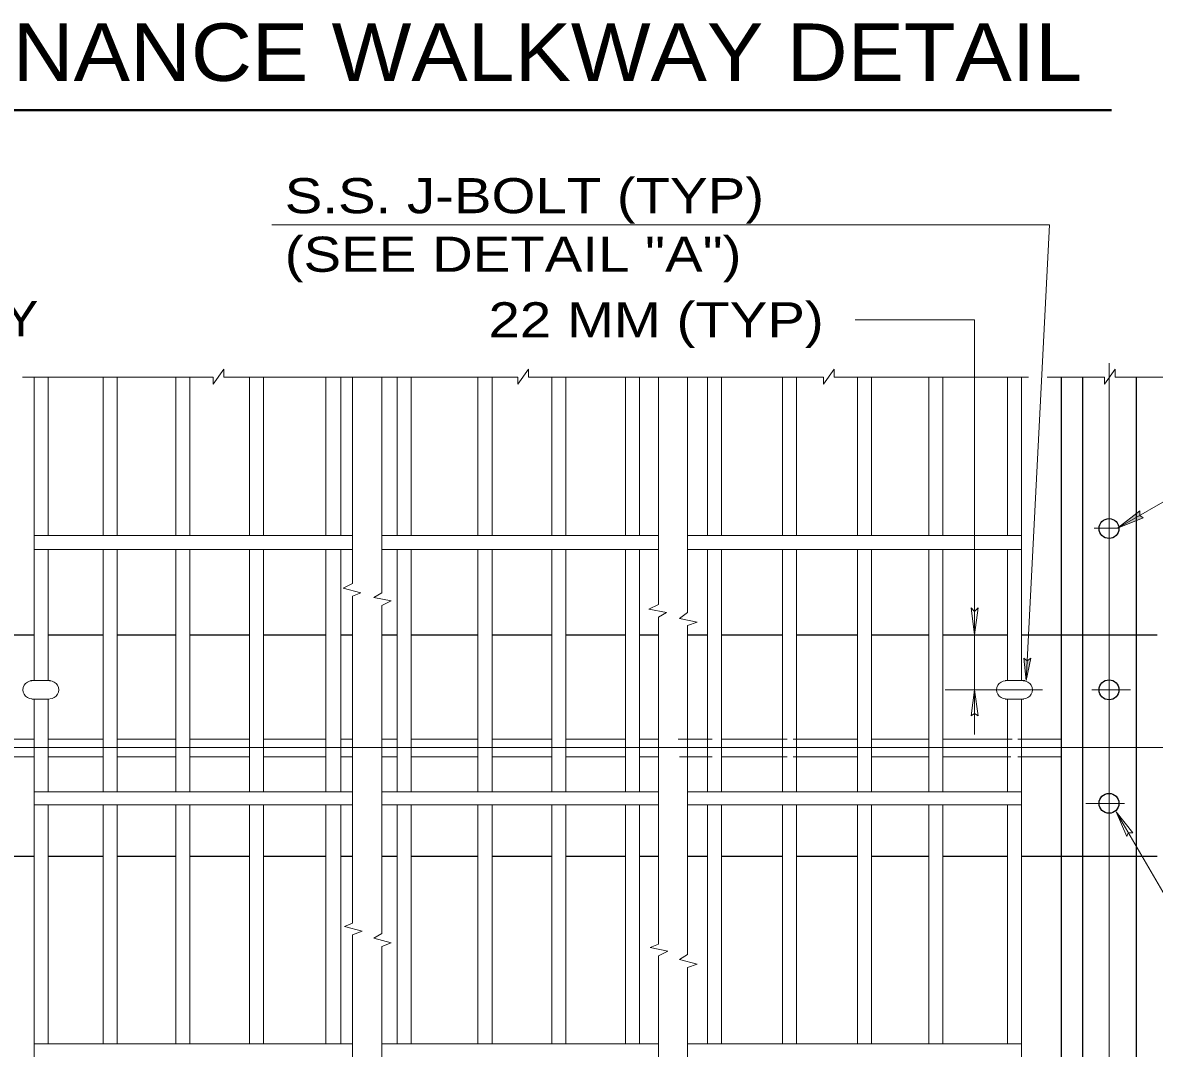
# Model space of a CAD drawing. Extents: x 312601.858 to 312602.699, y 144420.109 to 144420.704.
# Drawn here: x 312602.0138 to 312602.1105, y 144420.3668 to 144420.4544 of the extents above; entities that cross this region are included whole.
import ezdxf

# ---------------------------------------------------------------- set-up
doc = ezdxf.new("R2010")
doc.units = 0
doc.header["$LTSCALE"] = 0.0012
doc.linetypes.add('DOT_DASHED', pattern=[7.7, 5, -1.2, 0.3, -1.2])
doc.linetypes.add('LONG_DASHED', pattern=[7.5, 6, -1.5])
for name, color, linetype, lineweight in [('1', 7, 'Continuous', 13), ('2', 7, 'Continuous', 13), ('39', 7, 'Continuous', 13)]:
    doc.layers.add(name, color=color, linetype=linetype, lineweight=lineweight)

msp = doc.modelspace()

# ---------------------------------------------------------------- hatches: boundary and pattern name
at = {"layer": '39'}
for points in [[(312602.1092, 144420.4123), (312602.1095, 144420.4121), (312602.1073, 144420.4112), (312602.1092, 144420.4127)], [(312602.0996, 144420.3999), (312602.0999, 144420.4001), (312602.0995, 144420.3982), (312602.0993, 144420.4001)]]:
    msp.add_hatch(color=256, dxfattribs=at).paths.add_polyline_path(points)

# ---------------------------------------------------------------- linework, layer by layer
at = {"layer": '1'}
for p, q in [((312602.0849, 144420.429), (312602.0951, 144420.429)), ((312602.0138, 144420.4241), (312602.0301, 144420.4241)), ((312602.0148, 144420.3982), (312602.0148, 144420.4241)), ((312602.016, 144420.4106), (312602.016, 144420.4241)), ((312602.0207, 144420.4106), (312602.0207, 144420.4241)), ((312602.0219, 144420.4106), (312602.0219, 144420.4241)), ((312602.0269, 144420.4106), (312602.0269, 144420.4241)), ((312602.0281, 144420.4106), (312602.0281, 144420.4241)), ((312602.0301, 144420.4235), (312602.031, 144420.4248)), ((312602.0301, 144420.4235), (312602.0301, 144420.4241)), ((312602.031, 144420.4241), (312602.031, 144420.4248)), ((312602.031, 144420.4241), (312602.0407, 144420.4241)), ((312602.0332, 144420.4106), (312602.0332, 144420.4241)), ((312602.0344, 144420.4106), (312602.0344, 144420.4241)), ((312602.0397, 144420.4106), (312602.0397, 144420.4241)), ((312602.0406, 144420.4241), (312602.0561, 144420.4241)), ((312602.041, 144420.4106), (312602.041, 144420.4241)), ((312602.042, 144420.4241), (312602.042, 144420.4065)), ((312602.0445, 144420.4241), (312602.0445, 144420.4057)), ((312602.0458, 144420.4106), (312602.0458, 144420.4241)), ((312602.047, 144420.4106), (312602.047, 144420.4241)), ((312602.0527, 144420.4106), (312602.0527, 144420.4241)), ((312602.0539, 144420.4106), (312602.0539, 144420.4241)), ((312602.0561, 144420.4235), (312602.057, 144420.4248)), ((312602.0561, 144420.4235), (312602.0561, 144420.4241)), ((312602.057, 144420.4241), (312602.057, 144420.4248)), ((312602.057, 144420.4241), (312602.0822, 144420.4241)), ((312602.059, 144420.4106), (312602.059, 144420.4241)), ((312602.0602, 144420.4106), (312602.0602, 144420.4241)), ((312602.0653, 144420.4106), (312602.0653, 144420.4241)), ((312602.0665, 144420.4106), (312602.0665, 144420.4241)), ((312602.0681, 144420.4241), (312602.0681, 144420.4047)), ((312602.0706, 144420.4241), (312602.0706, 144420.404)), ((312602.0723, 144420.4106), (312602.0723, 144420.4241)), ((312602.0735, 144420.4106), (312602.0735, 144420.4241)), ((312602.0787, 144420.4106), (312602.0787, 144420.4241)), ((312602.0799, 144420.4106), (312602.0799, 144420.4241)), ((312602.0822, 144420.4235), (312602.0831, 144420.4248)), ((312602.0822, 144420.4235), (312602.0822, 144420.4241)), ((312602.0831, 144420.4241), (312602.0831, 144420.4248)), ((312602.0831, 144420.4241), (312602.0997, 144420.4241)), ((312602.0851, 144420.4106), (312602.0851, 144420.4241)), ((312602.0863, 144420.4106), (312602.0863, 144420.4241)), ((312602.0912, 144420.4106), (312602.0912, 144420.4241)), ((312602.0924, 144420.4106), (312602.0924, 144420.4241)), ((312602.0979, 144420.4106), (312602.0979, 144420.4241)), ((312602.0991, 144420.3982), (312602.0991, 144420.4241)), ((312602.1013, 144420.4241), (312602.1062, 144420.4241)), ((312602.1062, 144420.4235), (312602.1071, 144420.4248)), ((312602.1062, 144420.4235), (312602.1062, 144420.4241)), ((312602.1071, 144420.4241), (312602.1071, 144420.4248)), ((312602.1071, 144420.4241), (312602.1129, 144420.4241)), ((312602.1073, 144420.4112), (312602.1203, 144420.4187)), ((312602.0148, 144420.4106), (312602.042, 144420.4106)), ((312602.0445, 144420.4106), (312602.0681, 144420.4106)), ((312602.0706, 144420.4106), (312602.0991, 144420.4106)), ((312602.0148, 144420.4094), (312602.0208, 144420.4094)), ((312602.016, 144420.3982), (312602.016, 144420.4094)), ((312602.0207, 144420.3887), (312602.0207, 144420.4094)), ((312602.0208, 144420.4094), (312602.042, 144420.4094)), ((312602.0219, 144420.3887), (312602.0219, 144420.4094)), ((312602.0269, 144420.3887), (312602.0269, 144420.4094)), ((312602.0281, 144420.3887), (312602.0281, 144420.4094)), ((312602.0332, 144420.3887), (312602.0332, 144420.4094)), ((312602.0344, 144420.3887), (312602.0344, 144420.4094)), ((312602.0397, 144420.3887), (312602.0397, 144420.4094)), ((312602.041, 144420.3887), (312602.041, 144420.4094)), ((312602.0445, 144420.4094), (312602.0681, 144420.4094)), ((312602.0458, 144420.3887), (312602.0458, 144420.4094)), ((312602.047, 144420.3887), (312602.047, 144420.4094)), ((312602.0527, 144420.3887), (312602.0527, 144420.4094)), ((312602.0539, 144420.3887), (312602.0539, 144420.4094)), ((312602.059, 144420.3887), (312602.059, 144420.4094)), ((312602.0602, 144420.3887), (312602.0602, 144420.4094)), ((312602.0653, 144420.3887), (312602.0653, 144420.4094)), ((312602.0665, 144420.3887), (312602.0665, 144420.4094)), ((312602.0706, 144420.4094), (312602.0991, 144420.4094)), ((312602.0723, 144420.3887), (312602.0723, 144420.4094)), ((312602.0735, 144420.3887), (312602.0735, 144420.4094)), ((312602.0787, 144420.3887), (312602.0787, 144420.4094)), ((312602.0799, 144420.3887), (312602.0799, 144420.4094)), ((312602.0851, 144420.3887), (312602.0851, 144420.4094)), ((312602.0863, 144420.3887), (312602.0863, 144420.4094)), ((312602.0912, 144420.3887), (312602.0912, 144420.4094)), ((312602.0924, 144420.3887), (312602.0924, 144420.4094)), ((312602.0979, 144420.3982), (312602.0979, 144420.4094)), ((312602.0412, 144420.4061), (312602.042, 144420.4065)), ((312602.0412, 144420.4061), (312602.0427, 144420.4057)), ((312602.042, 144420.4054), (312602.0427, 144420.4057)), ((312602.042, 144420.4054), (312602.042, 144420.3775)), ((312602.0438, 144420.4053), (312602.0445, 144420.4057)), ((312602.0438, 144420.4053), (312602.0453, 144420.405)), ((312602.0445, 144420.4046), (312602.0453, 144420.405)), ((312602.0445, 144420.4046), (312602.0445, 144420.3766)), ((312602.0673, 144420.4043), (312602.0681, 144420.4047)), ((312602.0673, 144420.4043), (312602.0688, 144420.404)), ((312602.0681, 144420.4036), (312602.0688, 144420.404)), ((312602.0699, 144420.4035), (312602.0706, 144420.404)), ((312602.0681, 144420.4036), (312602.0681, 144420.3757)), ((312602.0699, 144420.4035), (312602.0714, 144420.4032)), ((312602.0706, 144420.4029), (312602.0714, 144420.4032)), ((312602.0706, 144420.4029), (312602.0706, 144420.3748)), ((312602.0145, 144420.3982), (312602.0162, 144420.3982)), ((312602.0977, 144420.3982), (312602.0994, 144420.3982)), ((312602.0146, 144420.3966), (312602.0161, 144420.3966)), ((312602.0148, 144420.3885), (312602.0148, 144420.3966)), ((312602.016, 144420.3887), (312602.016, 144420.3966)), ((312602.0977, 144420.3966), (312602.0993, 144420.3966)), ((312602.0979, 144420.3887), (312602.0979, 144420.3966)), ((312602.0991, 144420.3512), (312602.0991, 144420.3966)), ((312602.0148, 144420.3655), (312602.0148, 144420.3887)), ((312602.0148, 144420.3887), (312602.042, 144420.3887)), ((312602.0445, 144420.3887), (312602.0681, 144420.3887)), ((312602.0706, 144420.3887), (312602.0991, 144420.3887)), ((312602.0148, 144420.3876), (312602.042, 144420.3876)), ((312602.016, 144420.3672), (312602.016, 144420.3876)), ((312602.0207, 144420.3672), (312602.0207, 144420.3876)), ((312602.0219, 144420.3672), (312602.0219, 144420.3876)), ((312602.0269, 144420.3672), (312602.0269, 144420.3876)), ((312602.0281, 144420.3672), (312602.0281, 144420.3876)), ((312602.0332, 144420.3672), (312602.0332, 144420.3876)), ((312602.0344, 144420.3672), (312602.0344, 144420.3876)), ((312602.0397, 144420.3672), (312602.0397, 144420.3876)), ((312602.041, 144420.3672), (312602.041, 144420.3876)), ((312602.0445, 144420.3876), (312602.0681, 144420.3876)), ((312602.0458, 144420.3672), (312602.0458, 144420.3876)), ((312602.047, 144420.3672), (312602.047, 144420.3876)), ((312602.0527, 144420.3672), (312602.0527, 144420.3876)), ((312602.0539, 144420.3672), (312602.0539, 144420.3876)), ((312602.059, 144420.3672), (312602.059, 144420.3876)), ((312602.0602, 144420.3672), (312602.0602, 144420.3876)), ((312602.0653, 144420.3672), (312602.0653, 144420.3876)), ((312602.0665, 144420.3672), (312602.0665, 144420.3876)), ((312602.0706, 144420.3876), (312602.0991, 144420.3876)), ((312602.0723, 144420.3672), (312602.0723, 144420.3876)), ((312602.0735, 144420.3672), (312602.0735, 144420.3876)), ((312602.0787, 144420.3672), (312602.0787, 144420.3876)), ((312602.0799, 144420.3672), (312602.0799, 144420.3876)), ((312602.0851, 144420.3672), (312602.0851, 144420.3876)), ((312602.0863, 144420.3672), (312602.0863, 144420.3876)), ((312602.0912, 144420.3672), (312602.0912, 144420.3876)), ((312602.0924, 144420.3672), (312602.0924, 144420.3876)), ((312602.0979, 144420.3672), (312602.0979, 144420.3876)), ((312602.1072, 144420.387), (312602.1166, 144420.3708)), ((312602.0413, 144420.3772), (312602.042, 144420.3775)), ((312602.0413, 144420.3772), (312602.0428, 144420.3768)), ((312602.042, 144420.3765), (312602.0428, 144420.3768)), ((312602.042, 144420.3765), (312602.042, 144420.3528)), ((312602.0438, 144420.3762), (312602.0445, 144420.3766)), ((312602.0438, 144420.3762), (312602.0453, 144420.3758)), ((312602.0445, 144420.3755), (312602.0453, 144420.3758)), ((312602.0445, 144420.3755), (312602.0445, 144420.3522)), ((312602.0674, 144420.3754), (312602.0681, 144420.3757)), ((312602.0674, 144420.3754), (312602.0689, 144420.3751)), ((312602.0681, 144420.3747), (312602.0689, 144420.3751)), ((312602.0699, 144420.3744), (312602.0706, 144420.3748)), ((312602.0681, 144420.3747), (312602.0681, 144420.3476)), ((312602.0699, 144420.3744), (312602.0714, 144420.374)), ((312602.0706, 144420.3737), (312602.0714, 144420.374)), ((312602.0706, 144420.3737), (312602.0706, 144420.3473)), ((312602.0148, 144420.3672), (312602.042, 144420.3672)), ((312602.0445, 144420.3672), (312602.0681, 144420.3672)), ((312602.0706, 144420.3672), (312602.0991, 144420.3672))]:
    msp.add_line(p, q, dxfattribs=at)
at = {"layer": '1', "linetype": 'DOT_DASHED'}
for p, q in [((312602.1066, 144420.4253), (312602.1066, 144420.2757)), ((312602.1053, 144420.4112), (312602.1074, 144420.4112)), ((312602.0926, 144420.3974), (312602.1009, 144420.3974)), ((312602.1051, 144420.3974), (312602.1084, 144420.3974)), ((312601.9285, 144420.3925), (312602.0203, 144420.3925)), ((312602.0203, 144420.3925), (312602.0267, 144420.3925)), ((312602.0265, 144420.3925), (312602.1139, 144420.3925)), ((312602.1046, 144420.3877), (312602.1079, 144420.3877))]:
    msp.add_line(p, q, dxfattribs=at)
at = {"layer": '1', "lineweight": 25}
for p, q in [((312602.1025, 144420.4241), (312602.1025, 144420.3518)), ((312602.1043, 144420.4241), (312602.1043, 144420.3633)), ((312602.1089, 144420.4241), (312602.1089, 144420.3633)), ((312602.0081, 144420.4021), (312602.0148, 144420.4021)), ((312602.0219, 144420.4021), (312602.0269, 144420.4021)), ((312602.0281, 144420.4021), (312602.0332, 144420.4021)), ((312602.0344, 144420.4021), (312602.0397, 144420.4021)), ((312602.041, 144420.4021), (312602.042, 144420.4021)), ((312602.0445, 144420.4021), (312602.0458, 144420.4021)), ((312602.047, 144420.4021), (312602.0527, 144420.4021)), ((312602.0539, 144420.4021), (312602.059, 144420.4021)), ((312602.0602, 144420.4021), (312602.0653, 144420.4021)), ((312602.0665, 144420.4021), (312602.0681, 144420.4021)), ((312602.0706, 144420.4021), (312602.0723, 144420.4021)), ((312602.0735, 144420.4021), (312602.0787, 144420.4021)), ((312602.0799, 144420.4021), (312602.0851, 144420.4021)), ((312602.0863, 144420.4021), (312602.0912, 144420.4021)), ((312602.0924, 144420.4021), (312602.0979, 144420.4021)), ((312602.0991, 144420.4021), (312602.1025, 144420.4021)), ((312602.0081, 144420.3832), (312602.0148, 144420.3832)), ((312602.016, 144420.3832), (312602.0207, 144420.3832)), ((312602.0219, 144420.3832), (312602.0269, 144420.3832)), ((312602.0281, 144420.3832), (312602.0332, 144420.3832)), ((312602.0344, 144420.3832), (312602.0397, 144420.3832)), ((312602.041, 144420.3832), (312602.042, 144420.3832)), ((312602.0445, 144420.3832), (312602.0458, 144420.3832)), ((312602.047, 144420.3832), (312602.0527, 144420.3832)), ((312602.0539, 144420.3832), (312602.059, 144420.3832)), ((312602.0602, 144420.3832), (312602.0653, 144420.3832)), ((312602.0665, 144420.3832), (312602.0681, 144420.3832)), ((312602.0706, 144420.3832), (312602.0723, 144420.3832)), ((312602.0735, 144420.3832), (312602.0787, 144420.3832)), ((312602.0799, 144420.3832), (312602.0851, 144420.3832)), ((312602.0863, 144420.3832), (312602.0912, 144420.3832)), ((312602.0924, 144420.3832), (312602.0979, 144420.3832)), ((312602.0991, 144420.3832), (312602.1025, 144420.3832))]:
    msp.add_line(p, q, dxfattribs=at)
at = {"layer": '1', "linetype": 'LONG_DASHED', "lineweight": 25}
for p, q in [((312602.1025, 144420.4021), (312602.1107, 144420.4021)), ((312602.1025, 144420.3832), (312602.1107, 144420.3832))]:
    msp.add_line(p, q, dxfattribs=at)
at = {"layer": '1', "linetype": 'LONG_DASHED'}
for p, q in [((312602.0081, 144420.3932), (312602.0148, 144420.3932)), ((312602.016, 144420.3932), (312602.0207, 144420.3932)), ((312602.0219, 144420.3932), (312602.0269, 144420.3932)), ((312602.0281, 144420.3932), (312602.0332, 144420.3932)), ((312602.0344, 144420.3932), (312602.0397, 144420.3932)), ((312602.041, 144420.3932), (312602.042, 144420.3932)), ((312602.0445, 144420.3932), (312602.0458, 144420.3932)), ((312602.047, 144420.3932), (312602.0527, 144420.3932)), ((312602.0539, 144420.3932), (312602.059, 144420.3932)), ((312602.0602, 144420.3932), (312602.0653, 144420.3932)), ((312602.0665, 144420.3932), (312602.0681, 144420.3932)), ((312602.0698, 144420.3932), (312602.0727, 144420.3932)), ((312602.0735, 144420.3932), (312602.0791, 144420.3932)), ((312602.0796, 144420.3932), (312602.0851, 144420.3932)), ((312602.0863, 144420.3932), (312602.0912, 144420.3932)), ((312602.0924, 144420.3932), (312602.0983, 144420.3932)), ((312602.0988, 144420.3932), (312602.1025, 144420.3932)), ((312602.0081, 144420.3917), (312602.0148, 144420.3917)), ((312602.016, 144420.3917), (312602.0207, 144420.3917)), ((312602.0219, 144420.3917), (312602.0269, 144420.3917)), ((312602.0281, 144420.3917), (312602.0332, 144420.3917)), ((312602.0344, 144420.3917), (312602.0397, 144420.3917)), ((312602.041, 144420.3917), (312602.042, 144420.3917)), ((312602.0445, 144420.3917), (312602.0458, 144420.3917)), ((312602.047, 144420.3917), (312602.0527, 144420.3917)), ((312602.0539, 144420.3917), (312602.059, 144420.3917)), ((312602.0602, 144420.3917), (312602.0653, 144420.3917)), ((312602.0665, 144420.3917), (312602.0681, 144420.3917)), ((312602.0699, 144420.3917), (312602.0727, 144420.3917)), ((312602.0735, 144420.3917), (312602.0791, 144420.3917)), ((312602.0796, 144420.3917), (312602.0851, 144420.3917)), ((312602.0863, 144420.3917), (312602.0912, 144420.3917)), ((312602.0924, 144420.3917), (312602.0982, 144420.3917)), ((312602.0988, 144420.3917), (312602.1025, 144420.3917))]:
    msp.add_line(p, q, dxfattribs=at)
at = {"layer": '1'}
for points in [[(312602.0954, 144420.4044), (312602.0951, 144420.4021), (312602.0948, 144420.4044), (312602.0951, 144420.4041)], [(312602.0948, 144420.3952), (312602.0951, 144420.3974), (312602.0954, 144420.3952), (312602.0951, 144420.3954)], [(312602.1081, 144420.3849), (312602.1072, 144420.387), (312602.1086, 144420.3852), (312602.1082, 144420.3852)]]:
    msp.add_lwpolyline(points, close=True, dxfattribs=at)
at = {"layer": '1', "lineweight": 25}
msp.add_lwpolyline([(312602.016, 144420.4021), (312602.0172, 144420.4021), (312602.0207, 144420.4021)], dxfattribs=at)
for centre in [(312602.10658, 144420.41118), (312602.10658, 144420.39741), (312602.10658, 144420.38772)]:
    msp.add_circle(centre, 0.00085, dxfattribs=at)
at = {"layer": '1'}
for centre, start, end in [((312602.01461, 144420.39741), 89.22166, 270), ((312602.01614, 144420.39741), 270, 90.77834), ((312602.09774, 144420.39741), 89.22166, 270), ((312602.09927, 144420.39741), 270, 90.77834)]:
    msp.add_arc(centre, 0.000765, start, end, dxfattribs=at)
at = {"layer": '2', "lineweight": 40}
msp.add_line((312601.953, 144420.4469), (312602.1068, 144420.4469), dxfattribs=at)
at = {"layer": '2'}
for p in [(312602.0351, 144420.4371), (312602.0995, 144420.3982)]:
    msp.add_line(p, (312602.1015, 144420.4371), dxfattribs=at)
msp.add_lwpolyline([(312602.0951, 144420.3936), (312602.0951, 144420.3974), (312602.0951, 144420.4021), (312602.0951, 144420.429)], dxfattribs=at)
at = {"layer": '39'}
for points in [[(312602.1092, 144420.4123), (312602.1095, 144420.4121), (312602.1073, 144420.4112), (312602.1092, 144420.4127)], [(312602.0996, 144420.3999), (312602.0999, 144420.4001), (312602.0995, 144420.3982), (312602.0993, 144420.4001)]]:
    msp.add_lwpolyline(points, close=True, dxfattribs=at)

# ---------------------------------------------------------------- texts
at = {"layer": '2'}
for s, height, width, p in [('TYPICAL MAINTENANCE WALKWAY DETAIL', 0.0049, 1.1, (312601.9537, 144420.4494)), ('S.S. J-BOLT (TYP)', 0.003, 1.2, (312602.0362, 144420.4381)), ('(SEE DETAIL "A")', 0.003, 1.2, (312602.0362, 144420.4331)), ('LUMINAIRE AND WALKWAY', 0.003, 1.1, (312601.9568, 144420.4276)), ('22 MM (TYP)', 0.003, 1.2, (312602.0536, 144420.4275))]:
    msp.add_text(s, height=height, dxfattribs=dict(at, width=width)).set_placement(p)

doc.saveas('drawing.dxf')
